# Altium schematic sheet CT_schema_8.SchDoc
size 287 x 160 mm
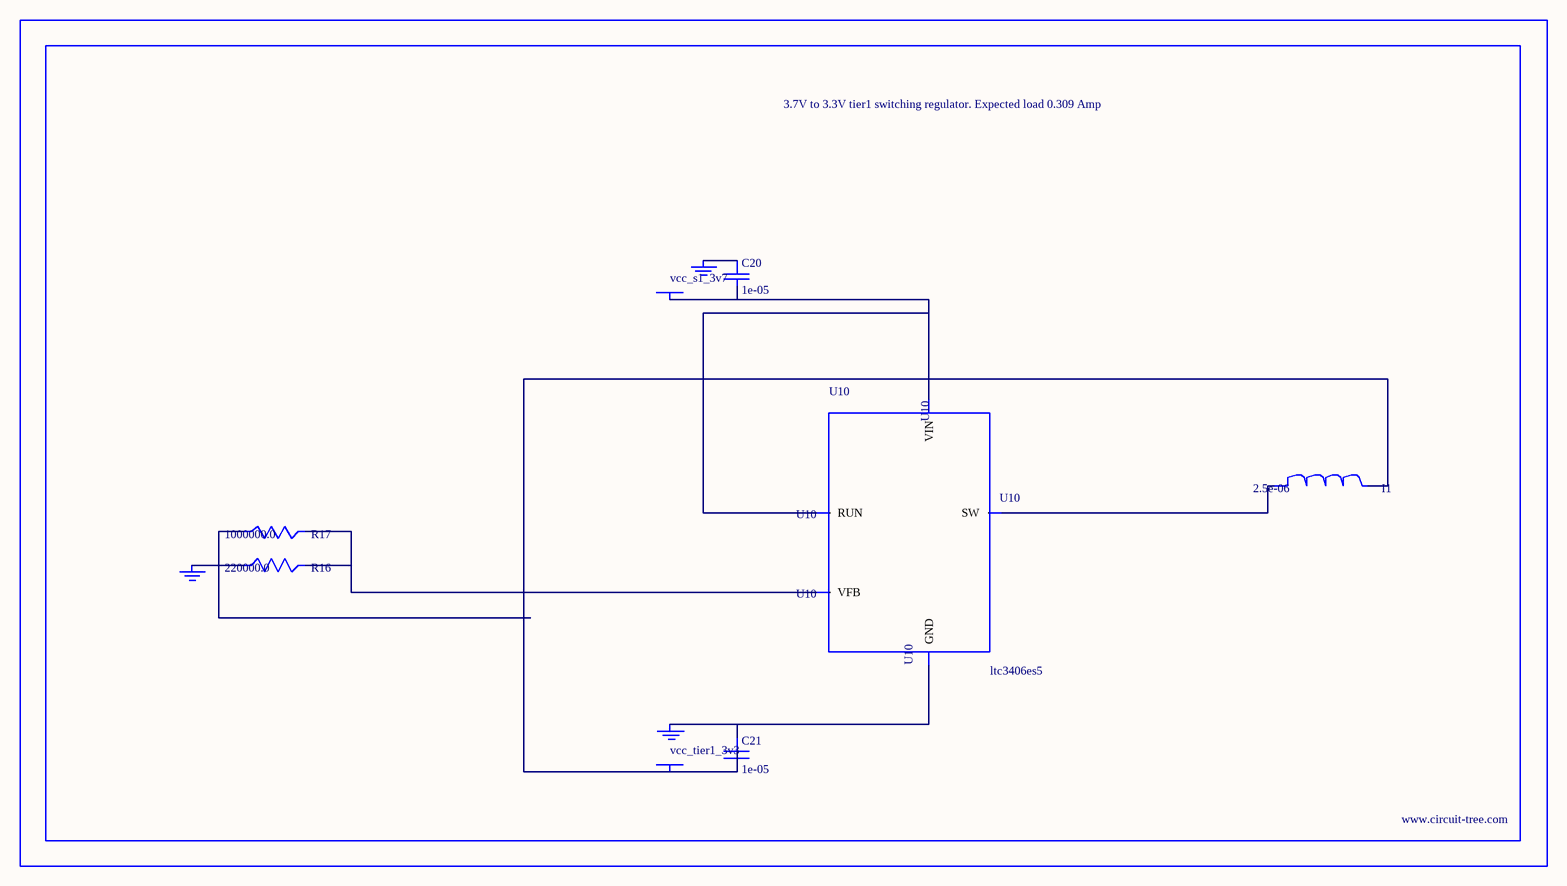
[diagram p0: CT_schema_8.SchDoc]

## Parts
BORDER7  (no value)
C20  1e-05  [C0805]
C21  1e-05  [C0805]
GND_INSTANCE_7_0  (no value)
GND_INSTANCE_7_1  (no value)
GND_INSTANCE_7_2  (no value)
I1  2.5e-06  [DR1040]
POWER_INSTANCE_7_0  vcc_tier1_3v3
POWER_INSTANCE_7_1  vcc_s1_3v7
R16  220000.0  [R0603]
R17  1000000.0  [R0603]
U10  ltc3406es5  [TSOT-23-5]

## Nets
NetC20_1: C20.1 GND_INSTANCE_7_1.0(GND)
NetC20_2: C20.2 POWER_INSTANCE_7_1.0(PWR) U10.1(RUN) U10.4(VIN)
NetC21_1: C21.1 GND_INSTANCE_7_0.0(GND) U10.2(GND)
NetC21_2: C21.2 I1.2 POWER_INSTANCE_7_0.0(PWR) R17.1
NetGND_INSTANCE_7_2_0: GND_INSTANCE_7_2.0(GND) R16.1
NetI1_1: I1.1 U10.3(SW)
NetR16_2: R16.2 R17.2 U10.5(VFB)

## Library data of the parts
BORDER7 = BORDER_PAGE7
C20 C21 = C0805C106K8RACTU
GND_INSTANCE_7_0-GND_INSTANCE_7_2 = GND
I1 = DR1040-2R5-R
POWER_INSTANCE_7_0 POWER_INSTANCE_7_1 = PWR
R16 = RC0603JR-07220KL
R17 = RC0603JR-071ML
